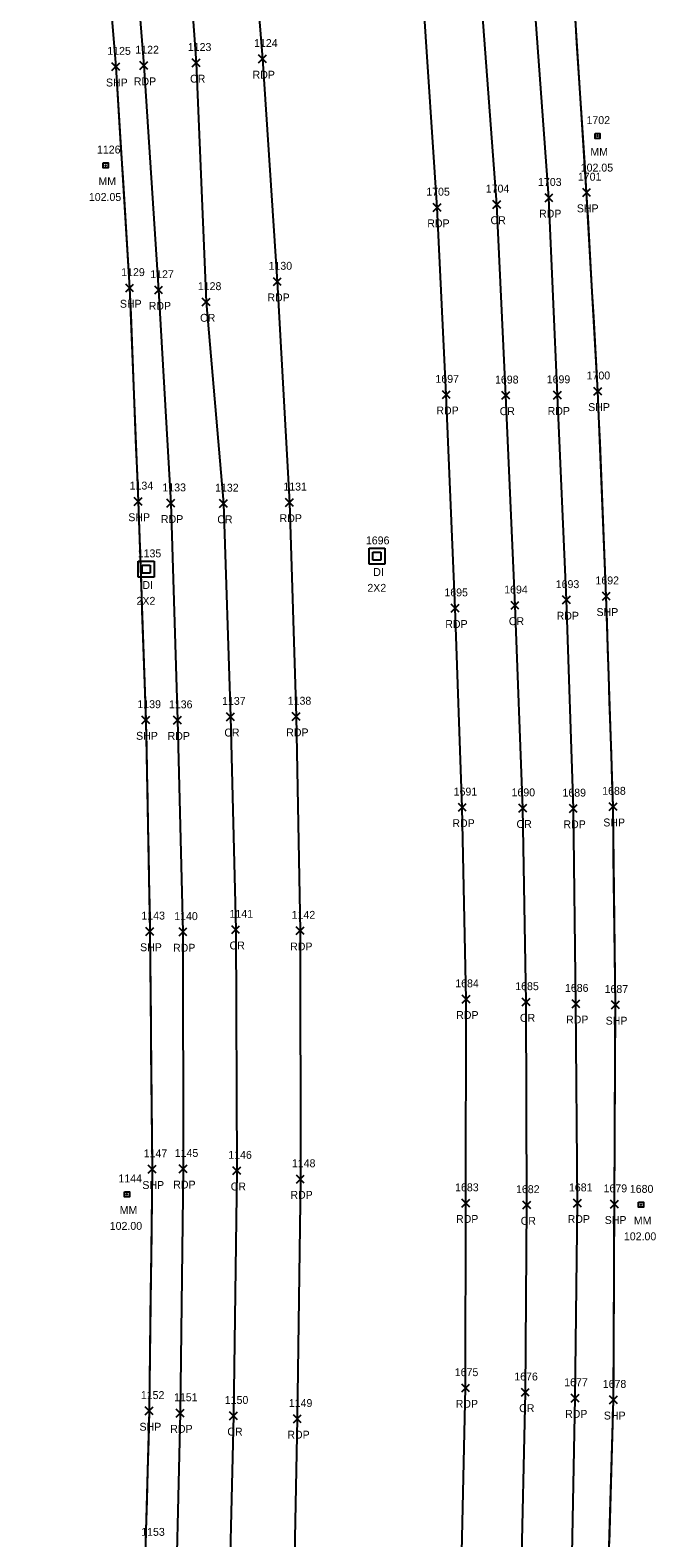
# Model space of a CAD drawing. Extents: x 1472022 to 1479249, y 777216 to 786527.
# Drawn here: x 1473882.5 to 1474040.7, y 781553.3 to 781934.6 of the extents above; entities that cross this region are included whole.
import ezdxf

# ---------------------------------------------------------------- set-up
doc = ezdxf.new("R2010")
doc.units = 0
for name, color, linetype in [('D_A', 7, 'Continuous'), ('D_C', 7, 'Continuous'), ('D_I', 7, 'Continuous'), ('DS', 7, 'Continuous'), ('LSOGP', 7, 'Continuous'), ('P_A', 7, 'Continuous'), ('P_I', 7, 'Continuous'), ('P_TIC', 7, 'Continuous'), ('PET', 7, 'Continuous'), ('PRC', 7, 'Continuous'), ('PSP', 7, 'Continuous'), ('S_A', 7, 'Continuous'), ('S_C', 7, 'Continuous'), ('S_I', 7, 'Continuous'), ('SRM', 7, 'Continuous')]:
    doc.layers.add(name, color=color, linetype=linetype)

msp = doc.modelspace()

# ---------------------------------------------------------------- linework, layer by layer
at = {"layer": 'DS'}
for p, q in [((1473968.2, 781803.55), (1473972.2, 781803.55)), ((1473968.2, 781799.55), (1473968.2, 781803.55)), ((1473969.2, 781800.55), (1473969.2, 781802.55)), ((1473969.2, 781802.55), (1473971.2, 781802.55)), ((1473970.2, 781801.55), (1473970.2, 781801.55)), ((1473970.2, 781801.55), (1473970.2, 781801.55)), ((1473971.2, 781802.55), (1473971.2, 781800.55)), ((1473972.2, 781803.55), (1473972.2, 781799.55)), ((1473909.84, 781800.26), (1473913.84, 781800.26)), ((1473909.84, 781796.26), (1473909.84, 781800.26)), ((1473910.84, 781797.26), (1473910.84, 781799.26)), ((1473910.84, 781799.26), (1473912.84, 781799.26)), ((1473912.84, 781797.26), (1473910.84, 781797.26)), ((1473911.84, 781798.26), (1473911.84, 781798.26)), ((1473911.84, 781798.26), (1473911.84, 781798.26)), ((1473912.84, 781799.26), (1473912.84, 781797.26)), ((1473913.84, 781800.26), (1473913.84, 781796.26)), ((1473972.2, 781799.55), (1473968.2, 781799.55)), ((1473971.2, 781800.55), (1473969.2, 781800.55)), ((1473913.84, 781796.26), (1473909.84, 781796.26))]:
    msp.add_line(p, q, dxfattribs=at)
at = {"layer": 'LSOGP'}
for points in [[(1473902.98, 781939.58), (1473903.57, 781932.45), (1473904.16, 781925.33), (1473904.6, 781918.34), (1473905.04, 781911.34), (1473905.48, 781904.35), (1473905.92, 781897.35), (1473906.36, 781890.36), (1473906.8, 781883.37), (1473907.24, 781876.37), (1473907.68, 781869.38), (1473907.95, 781862.63), (1473908.21, 781855.88), (1473908.48, 781849.14), (1473908.74, 781842.39), (1473909.01, 781835.64), (1473909.27, 781828.89), (1473909.54, 781822.15), (1473909.81, 781815.4), (1473910.05, 781808.49), (1473910.3, 781801.58), (1473910.55, 781794.67), (1473910.79, 781787.76), (1473911.04, 781780.85), (1473911.29, 781773.95), (1473911.53, 781767.04), (1473911.9, 781753.45), (1473912.03, 781746.76), (1473912.16, 781740.08), (1473912.28, 781733.4), (1473912.41, 781726.72), (1473912.54, 781720.04), (1473912.66, 781713.35), (1473912.79, 781706.67), (1473912.86, 781699.16), (1473912.93, 781691.64), (1473913, 781684.13), (1473913.07, 781676.61), (1473913.14, 781669.1), (1473913.21, 781661.58), (1473913.28, 781654.07), (1473913.35, 781646.55), (1473913.26, 781638.91), (1473913.17, 781631.27), (1473913.08, 781623.63), (1473912.99, 781615.98), (1473912.9, 781608.34), (1473912.81, 781600.7), (1473912.72, 781593.06), (1473912.63, 781585.42), (1473912.42, 781577.85), (1473912.21, 781570.29), (1473912, 781562.73), (1473911.79, 781555.16), (1473911.57, 781547.6)], [(1474028.95, 781551.9), (1474029.13, 781557.95), (1474029.31, 781564.01), (1474029.49, 781570.07), (1474029.67, 781576.13), (1474029.84, 781582.19), (1474030.02, 781588.25), (1474030.05, 781594.43), (1474030.08, 781600.61), (1474030.11, 781606.79), (1474030.13, 781612.97), (1474030.16, 781619.16), (1474030.19, 781625.34), (1474030.21, 781631.52), (1474030.24, 781637.7), (1474030.27, 781644), (1474030.3, 781650.3), (1474030.33, 781656.6), (1474030.36, 781662.9), (1474030.39, 781669.2), (1474030.43, 781675.5), (1474030.46, 781681.8), (1474030.49, 781688.1), (1474030.41, 781694.37), (1474030.34, 781700.63), (1474030.26, 781706.9), (1474030.19, 781713.16), (1474030.11, 781719.42), (1474030.04, 781725.69), (1474029.96, 781731.95), (1474029.89, 781738.22), (1474029.67, 781744.87), (1474029.46, 781751.52), (1474029.25, 781758.17), (1474029.03, 781764.82), (1474028.82, 781771.47), (1474028.61, 781778.13), (1474028.39, 781784.78), (1474028.18, 781791.43), (1474027.91, 781797.91), (1474027.65, 781804.38), (1474027.39, 781810.86), (1474027.12, 781817.34), (1474026.86, 781823.82), (1474026.59, 781830.3), (1474026.33, 781836.77), (1474026.06, 781843.25), (1474025.71, 781849.53), (1474025.35, 781855.81), (1474024.99, 781862.1), (1474024.63, 781868.38), (1474024.28, 781874.66), (1474023.92, 781880.94), (1474023.56, 781887.22), (1474023.21, 781893.51), (1474022.8, 781899.79), (1474022.39, 781906.08), (1474021.99, 781912.37), (1474021.58, 781918.66), (1474021.18, 781924.95), (1474020.77, 781931.24), (1474020.37, 781937.53)]]:
    msp.add_lwpolyline(points, dxfattribs=at)
at = {"layer": 'P_TIC'}
for points in [[(1473910.24, 781924.62), (1473912.24, 781926.62)], [(1473912.24, 781924.62), (1473910.24, 781926.62)], [(1473923.52, 781925.3), (1473925.52, 781927.3)], [(1473925.52, 781925.3), (1473923.52, 781927.3)], [(1473940.26, 781926.31), (1473942.26, 781928.31)], [(1473942.26, 781926.31), (1473940.26, 781928.31)], [(1473903.16, 781924.33), (1473905.16, 781926.33)], [(1473905.16, 781924.33), (1473903.16, 781926.33)], [(1474012.69, 781891.18), (1474014.69, 781893.18)], [(1474014.69, 781891.18), (1474012.69, 781893.18)], [(1474022.21, 781892.51), (1474024.21, 781894.51)], [(1474024.21, 781892.51), (1474022.21, 781894.51)], [(1473984.44, 781888.72), (1473986.44, 781890.72)], [(1473986.44, 781888.72), (1473984.44, 781890.72)], [(1473999.48, 781889.51), (1474001.48, 781891.51)], [(1474001.48, 781889.51), (1473999.48, 781891.51)], [(1473906.68, 781868.38), (1473908.68, 781870.38)], [(1473908.68, 781868.38), (1473906.68, 781870.38)], [(1473914.01, 781867.86), (1473916.01, 781869.86)], [(1473916.01, 781867.86), (1473914.01, 781869.86)], [(1473944.01, 781869.98), (1473946.01, 781871.98)], [(1473946.01, 781869.98), (1473944.01, 781871.98)], [(1473926.05, 781864.83), (1473928.05, 781866.83)], [(1473928.05, 781864.83), (1473926.05, 781866.83)], [(1473986.73, 781841.4), (1473988.73, 781843.4)], [(1473988.73, 781841.4), (1473986.73, 781843.4)], [(1474001.79, 781841.22), (1474003.79, 781843.22)], [(1474003.79, 781841.22), (1474001.79, 781843.22)], [(1474014.87, 781841.28), (1474016.87, 781843.28)], [(1474016.87, 781841.28), (1474014.87, 781843.28)], [(1474025.06, 781842.25), (1474027.06, 781844.25)], [(1474027.06, 781842.25), (1474025.06, 781844.25)], [(1473908.81, 781814.4), (1473910.81, 781816.4)], [(1473910.81, 781814.4), (1473908.81, 781816.4)], [(1473917.09, 781813.94), (1473919.09, 781815.94)], [(1473919.09, 781813.94), (1473917.09, 781815.94)], [(1473947.1, 781814.16), (1473949.1, 781816.16)], [(1473949.1, 781814.16), (1473947.1, 781816.16)], [(1473930.41, 781813.87), (1473932.41, 781815.87)], [(1473932.41, 781813.87), (1473930.41, 781815.87)], [(1473988.99, 781787.4), (1473990.99, 781789.4)], [(1473990.99, 781787.4), (1473988.99, 781789.4)], [(1474004.11, 781788.12), (1474006.11, 781790.12)], [(1474006.11, 781788.12), (1474004.11, 781790.12)], [(1474017.14, 781789.49), (1474019.14, 781791.49)], [(1474019.14, 781789.49), (1474017.14, 781791.49)], [(1474027.18, 781790.43), (1474029.18, 781792.43)], [(1474029.18, 781790.43), (1474027.18, 781792.43)], [(1473910.78, 781759.13), (1473912.78, 781761.13)], [(1473912.78, 781759.13), (1473910.78, 781761.13)], [(1473918.79, 781759.09), (1473920.79, 781761.09)], [(1473920.79, 781759.09), (1473918.79, 781761.09)], [(1473932.18, 781759.96), (1473934.18, 781761.96)], [(1473934.18, 781759.96), (1473932.18, 781761.96)], [(1473948.78, 781760), (1473950.78, 781762)], [(1473950.78, 781760), (1473948.78, 781762)], [(1473990.78, 781737.04), (1473992.78, 781739.04)], [(1473992.78, 781737.04), (1473990.78, 781739.04)], [(1474006.05, 781736.83), (1474008.05, 781738.83)], [(1474008.05, 781736.83), (1474006.05, 781738.83)], [(1474018.85, 781736.76), (1474020.85, 781738.76)], [(1474020.85, 781736.76), (1474018.85, 781738.76)], [(1474028.89, 781737.22), (1474030.89, 781739.22)], [(1474030.89, 781737.22), (1474028.89, 781739.22)], [(1473911.79, 781705.67), (1473913.79, 781707.67)], [(1473913.79, 781705.67), (1473911.79, 781707.67)], [(1473920.16, 781705.54), (1473922.16, 781707.54)], [(1473922.16, 781705.54), (1473920.16, 781707.54)], [(1473933.49, 781706.12), (1473935.49, 781708.12)], [(1473935.49, 781706.12), (1473933.49, 781708.12)], [(1473949.76, 781705.86), (1473951.76, 781707.86)], [(1473951.76, 781705.86), (1473949.76, 781707.86)], [(1473991.74, 781688.53), (1473993.74, 781690.53)], [(1473993.74, 781688.53), (1473991.74, 781690.53)], [(1474006.9, 781687.82), (1474008.9, 781689.82)], [(1474008.9, 781687.82), (1474006.9, 781689.82)], [(1474019.52, 781687.39), (1474021.52, 781689.39)], [(1474021.52, 781687.39), (1474019.52, 781689.39)], [(1474029.49, 781687.1), (1474031.49, 781689.1)], [(1474031.49, 781687.1), (1474029.49, 781689.1)], [(1473912.35, 781645.55), (1473914.35, 781647.55)], [(1473914.35, 781645.55), (1473912.35, 781647.55)], [(1473920.22, 781645.65), (1473922.22, 781647.65)], [(1473922.22, 781645.65), (1473920.22, 781647.65)], [(1473933.8, 781645.17), (1473935.8, 781647.17)], [(1473935.8, 781645.17), (1473933.8, 781647.17)], [(1473949.83, 781643.05), (1473951.83, 781645.05)], [(1473951.83, 781643.05), (1473949.83, 781645.05)], [(1473991.7, 781636.96), (1473993.7, 781638.96)], [(1473993.7, 781636.96), (1473991.7, 781638.96)], [(1474007.1, 781636.49), (1474009.1, 781638.49)], [(1474009.1, 781636.49), (1474007.1, 781638.49)], [(1474019.92, 781636.94), (1474021.92, 781638.94)], [(1474021.92, 781636.94), (1474019.92, 781638.94)], [(1474029.24, 781636.7), (1474031.24, 781638.7)], [(1474031.24, 781636.7), (1474029.24, 781638.7)], [(1473991.62, 781590.22), (1473993.62, 781592.22)], [(1473993.62, 781590.22), (1473991.62, 781592.22)], [(1474006.72, 781589.12), (1474008.72, 781591.12)], [(1474008.72, 781589.12), (1474006.72, 781591.12)], [(1474019.28, 781587.67), (1474021.28, 781589.67)], [(1474021.28, 781587.67), (1474019.28, 781589.67)], [(1474029.02, 781587.25), (1474031.02, 781589.25)], [(1474031.02, 781587.25), (1474029.02, 781589.25)], [(1473911.63, 781584.42), (1473913.63, 781586.42)], [(1473913.63, 781584.42), (1473911.63, 781586.42)], [(1473919.46, 781583.88), (1473921.46, 781585.88)], [(1473921.46, 781583.88), (1473919.46, 781585.88)], [(1473932.94, 781583.19), (1473934.94, 781585.19)], [(1473934.94, 781583.19), (1473932.94, 781585.19)], [(1473949.06, 781582.41), (1473951.06, 781584.41)], [(1473951.06, 781582.41), (1473949.06, 781584.41)]]:
    msp.add_lwpolyline(points, dxfattribs=at)
at = {"layer": 'PET'}
for points in [[(1473936.65, 781984.46), (1473941.26, 781927.31), (1473945.01, 781870.98), (1473948.1, 781815.16), (1473949.78, 781761), (1473950.76, 781706.86), (1473950.83, 781644.05), (1473950.06, 781583.41), (1473948.84, 781522.99), (1473946.53, 781467.74), (1473942.83, 781404.05), (1473938.3, 781346.37), (1473932.98, 781286.88), (1473926.74, 781228.4), (1473920.04, 781167.79)], [(1473906.73, 781982.64), (1473911.24, 781925.62), (1473915.01, 781868.86), (1473918.09, 781814.94), (1473919.79, 781760.09), (1473921.16, 781706.54), (1473921.22, 781646.65), (1473920.46, 781584.88), (1473919, 781524.8), (1473916.99, 781468.11), (1473913.78, 781408.07), (1473908.72, 781348.11), (1473904.17, 781290.69), (1473897.58, 781231.34), (1473890.82, 781171.41)], [(1473960.11, 781159.28), (1473966.39, 781210.69), (1473970.91, 781249.41), (1473976.53, 781307.15), (1473980.69, 781352.24), (1473984.63, 781407.6), (1473987.74, 781461.59), (1473990.05, 781507.23), (1473991.52, 781542.09), (1473992.62, 781591.22), (1473992.7, 781637.96), (1473992.74, 781689.53), (1473991.78, 781738.04), (1473989.99, 781788.4), (1473987.73, 781842.4), (1473985.44, 781889.72), (1473981.98, 781941.8)], [(1473988.2, 781155.74), (1473994.49, 781207.67), (1473999, 781245.64), (1474004.6, 781303.34), (1474009, 781350.44), (1474012.88, 781405.45), (1474016.36, 781459.96), (1474018.02, 781505.8), (1474019.41, 781540.51), (1474020.28, 781588.67), (1474020.92, 781637.94), (1474020.52, 781688.39), (1474019.85, 781737.76), (1474018.14, 781790.49), (1474015.87, 781842.28), (1474013.69, 781892.18), (1474009.96, 781943.03)]]:
    msp.add_lwpolyline(points, dxfattribs=at)
at = {"layer": 'PRC'}
for points in [[(1473920.36, 781983.62), (1473924.52, 781926.3), (1473927.05, 781865.83), (1473931.41, 781814.87), (1473933.18, 781760.96), (1473934.49, 781707.12), (1473934.8, 781646.17), (1473933.94, 781584.19), (1473932.54, 781524.63), (1473930.03, 781468.03), (1473926.7, 781406.41), (1473922.16, 781347.38), (1473917.13, 781289.55), (1473910.61, 781230.26), (1473903.7, 781169.35)], [(1473975.01, 781157.69), (1473981.49, 781209.1), (1473985.9, 781246.34), (1473992.15, 781304.78), (1473996, 781351.86), (1473999.89, 781406.19), (1474002.87, 781460.13), (1474005.19, 781506.03), (1474006.68, 781541.33), (1474007.72, 781590.12), (1474008.1, 781637.49), (1474007.9, 781688.82), (1474007.05, 781737.83), (1474005.11, 781789.12), (1474002.79, 781842.22), (1474000.48, 781890.51), (1473996.64, 781942.33)]]:
    msp.add_lwpolyline(points, dxfattribs=at)
at = {"layer": 'PSP'}
for points in [[(1473899.44, 781982.31), (1473904.16, 781925.33), (1473907.68, 781869.38), (1473909.81, 781815.4), (1473911.78, 781760.13), (1473912.79, 781706.67), (1473913.35, 781646.55), (1473912.63, 781585.42), (1473910.94, 781524.91), (1473908.69, 781468.23), (1473905.64, 781408.86), (1473901.06, 781348.62), (1473896.13, 781291.07), (1473889.69, 781232.26), (1473882.53, 781172.78)], [(1473997.41, 781153.76), (1474004.06, 781207.93), (1474007.89, 781244.71), (1474013.81, 781303.22), (1474018.17, 781349.54), (1474021.78, 781405.07), (1474025.02, 781458.79), (1474026.9, 781489.79), (1474028.59, 781539.78), (1474030.02, 781588.25), (1474030.24, 781637.7), (1474030.49, 781688.1), (1474029.89, 781738.22), (1474028.18, 781791.43), (1474026.06, 781843.25), (1474023.21, 781893.51), (1474019.96, 781943.82)]]:
    msp.add_lwpolyline(points, dxfattribs=at)
at = {"layer": 'SRM'}
for points in [[(1474025.33, 781908.44), (1474026.58, 781908.44), (1474026.58, 781907.19), (1474025.33, 781907.19)], [(1473900.98, 781901.01), (1473902.23, 781901.01), (1473902.23, 781899.76), (1473900.98, 781899.76)], [(1473906.35, 781640.83), (1473907.6, 781640.83), (1473907.6, 781639.58), (1473906.35, 781639.58)], [(1474036.33, 781638.19), (1474037.58, 781638.19), (1474037.58, 781636.94), (1474036.33, 781636.94)]]:
    msp.add_lwpolyline(points, close=True, dxfattribs=at)
for centre in [(1474025.95, 781907.81), (1473901.6, 781900.38), (1473906.97, 781640.21), (1474036.95, 781637.57)]:
    msp.add_circle(centre, 0.0833, dxfattribs=at)

# ---------------------------------------------------------------- texts
at = {"layer": 'D_A'}
for p in [(1473969.26, 781796.55), (1473910.9, 781793.26)]:
    msp.add_text('DI', height=2, dxfattribs=at).set_placement(p)
at = {"layer": 'D_C'}
for p in [(1473967.78, 781792.55), (1473909.42, 781789.26)]:
    msp.add_text('2X2', height=2, dxfattribs=at).set_placement(p)
at = {"layer": 'D_I'}
for s, p in [('1696', (1473967.41, 781804.55)), ('1135', (1473909.72, 781801.26)), ('1153', (1473910.61, 781553.84))]:
    msp.add_text(s, height=2, dxfattribs=at).set_placement(p)
at = {"layer": 'P_A'}
for s, p in [('CR', (1473922.95, 781921.3)), ('RDP', (1473938.75, 781922.31)), ('SHP', (1473901.69, 781920.33)), ('RDP', (1473908.73, 781920.62)), ('RDP', (1474011.18, 781887.18)), ('SHP', (1474020.74, 781888.51)), ('RDP', (1473982.93, 781884.72)), ('CR', (1473998.91, 781885.51)), ('SHP', (1473905.22, 781864.38)), ('RDP', (1473912.5, 781863.86)), ('RDP', (1473942.5, 781865.98)), ('CR', (1473925.48, 781860.83)), ('RDP', (1473985.22, 781837.4)), ('CR', (1474001.22, 781837.22)), ('RDP', (1474013.35, 781837.28)), ('SHP', (1474023.6, 781838.25)), ('SHP', (1473907.34, 781810.4)), ('RDP', (1473945.59, 781810.16)), ('RDP', (1473915.58, 781809.94)), ('CR', (1473929.84, 781809.87)), ('CR', (1474003.54, 781784.12)), ('RDP', (1474015.63, 781785.49)), ('SHP', (1474025.71, 781786.43)), ('RDP', (1473987.48, 781783.4)), ('SHP', (1473909.31, 781755.13)), ('RDP', (1473917.28, 781755.09)), ('CR', (1473931.61, 781755.96)), ('RDP', (1473947.26, 781756)), ('RDP', (1473989.27, 781733.04)), ('CR', (1474005.48, 781732.83)), ('RDP', (1474017.34, 781732.76)), ('SHP', (1474027.42, 781733.22)), ('SHP', (1473910.32, 781701.67)), ('RDP', (1473918.65, 781701.54)), ('CR', (1473932.93, 781702.12)), ('RDP', (1473948.25, 781701.86)), ('RDP', (1473990.23, 781684.53)), ('CR', (1474006.34, 781683.82)), ('RDP', (1474018.01, 781683.39)), ('SHP', (1474028.02, 781683.1)), ('SHP', (1473910.89, 781641.55)), ('RDP', (1473918.7, 781641.65)), ('CR', (1473933.23, 781641.17)), ('RDP', (1473948.32, 781639.05)), ('RDP', (1473990.19, 781632.96)), ('CR', (1474006.53, 781632.49)), ('RDP', (1474018.41, 781632.94)), ('SHP', (1474027.78, 781632.7)), ('RDP', (1473990.11, 781586.22)), ('CR', (1474006.15, 781585.12)), ('RDP', (1474017.76, 781583.67)), ('SHP', (1474027.56, 781583.25)), ('SHP', (1473910.17, 781580.42)), ('RDP', (1473917.95, 781579.88)), ('CR', (1473932.38, 781579.19)), ('RDP', (1473947.55, 781578.41))]:
    msp.add_text(s, height=2, dxfattribs=at).set_placement(p)
at = {"layer": 'P_I'}
for s, p in [('1125', (1473902.03, 781928.33)), ('1122', (1473909.12, 781928.62)), ('1123', (1473922.39, 781929.3)), ('1124', (1473939.14, 781930.31)), ('1703', (1474010.92, 781895.18)), ('1701', (1474021, 781896.51)), ('1705', (1473982.67, 781892.72)), ('1704', (1473997.71, 781893.51)), ('1129', (1473905.55, 781872.38)), ('1127', (1473912.89, 781871.86)), ('1130', (1473942.8, 781873.98)), ('1128', (1473924.92, 781868.83)), ('1697', (1473984.99, 781845.4)), ('1698', (1474000.05, 781845.22)), ('1699', (1474013.12, 781845.28)), ('1700', (1474023.21, 781846.25)), ('1134', (1473907.68, 781818.4)), ('1133', (1473915.97, 781817.94)), ('1132', (1473929.28, 781817.87)), ('1131', (1473946.54, 781818.16)), ('1695', (1473987.25, 781791.4)), ('1694', (1474002.37, 781792.12)), ('1693', (1474015.4, 781793.49)), ('1692', (1474025.44, 781794.43)), ('1139', (1473909.64, 781763.13)), ('1136', (1473917.61, 781763.09)), ('1137', (1473931.05, 781763.96)), ('1138', (1473947.65, 781764)), ('1691', (1473989.6, 781741.04)), ('1690', (1474004.22, 781740.83)), ('1689', (1474017.1, 781740.76)), ('1688', (1474027.15, 781741.22)), ('1143', (1473910.66, 781709.67)), ('1140', (1473918.95, 781709.54)), ('1141', (1473932.93, 781710.12)), ('1142', (1473948.64, 781709.86)), ('1684', (1473990, 781692.53)), ('1685', (1474005.16, 781691.82)), ('1686', (1474017.73, 781691.39)), ('1687', (1474027.75, 781691.1)), ('1147', (1473911.23, 781649.55)), ('1145', (1473919.09, 781649.65)), ('1146', (1473932.62, 781649.17)), ('1148', (1473948.7, 781647.05)), ('1683', (1473989.96, 781640.96)), ('1682', (1474005.36, 781640.49)), ('1681', (1474018.74, 781640.94)), ('1679', (1474027.49, 781640.7)), ('1675', (1473989.88, 781594.22)), ('1676', (1474004.92, 781593.12)), ('1677', (1474017.54, 781591.67)), ('1678', (1474027.28, 781591.25)), ('1152', (1473910.51, 781588.42)), ('1151', (1473918.9, 781587.88)), ('1150', (1473931.73, 781587.19)), ('1149', (1473947.92, 781586.41))]:
    msp.add_text(s, height=2, dxfattribs=at).set_placement(p)
at = {"layer": 'S_A'}
for p in [(1474024.14, 781902.81), (1473899.79, 781895.38), (1473905.16, 781635.21), (1474035.14, 781632.57)]:
    msp.add_text('MM', height=2, dxfattribs=at).set_placement(p)
at = {"layer": 'S_C'}
for s, p in [('102.05', (1474021.72, 781898.81)), ('102.05', (1473897.37, 781891.38)), ('102.00', (1473902.65, 781631.21)), ('102.00', (1474032.63, 781628.57))]:
    msp.add_text(s, height=2, dxfattribs=at).set_placement(p)
at = {"layer": 'S_I'}
for s, p in [('1702', (1474023.18, 781910.81)), ('1126', (1473899.42, 781903.38)), ('1144', (1473904.84, 781643.21)), ('1680', (1474034.13, 781640.57))]:
    msp.add_text(s, height=2, dxfattribs=at).set_placement(p)

doc.saveas('drawing.dxf')
